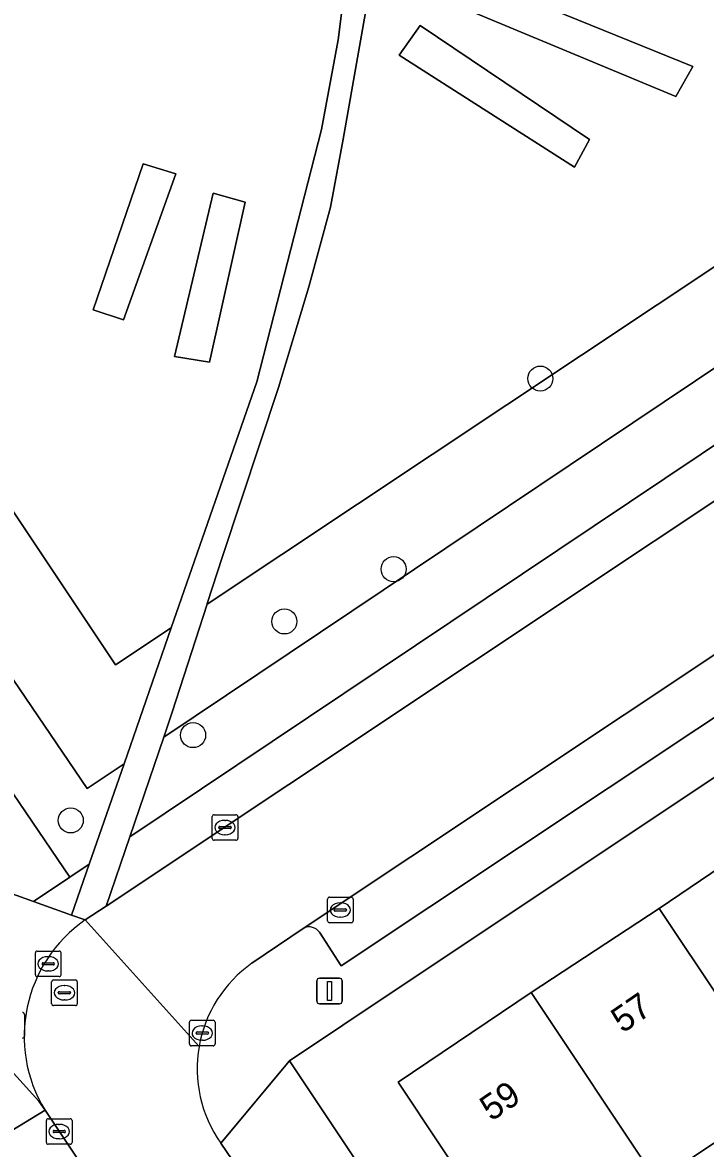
# Model space of a CAD drawing. Extents: x 158352 to 159489, y 383828 to 384603.
# Drawn here: x 158635.92 to 158662.61, y 384326.59 to 384370.6 of the extents above; entities that cross this region are included whole.
import ezdxf

# ---------------------------------------------------------------- set-up
doc = ezdxf.new("R2010")
doc.units = 0
for name, color, linetype in [('IMGEO_Boom', 7, 'Continuous'), ('IMGEO_Erf', 7, 'Continuous'), ('IMGEO_Groenvoorziening', 7, 'Continuous'), ('IMGEO_Kolk', 7, 'Continuous'), ('IMGEO_Lichtmast', 7, 'Continuous'), ('IMGEO_Pand', 7, 'Continuous'), ('IMGEO_Pand_nummerreeks', 7, 'Continuous'), ('IMGEO_Parkeervlak_open', 7, 'Continuous'), ('IMGEO_Rijbaan_lokaal_open', 7, 'Continuous'), ('IMGEO_Rioolput', 7, 'Continuous'), ('IMGEO_Voetpad_onverhard', 7, 'Continuous'), ('IMGEO_Voetpad_open', 7, 'Continuous')]:
    doc.layers.add(name, color=color, linetype=linetype)

msp = doc.modelspace()

# ---------------------------------------------------------------- linework, layer by layer
at = {"layer": 'IMGEO_Boom'}
for centre in [(158656.156, 384356.679), (158650.421, 384349.23), (158646.15, 384347.185), (158642.583, 384342.742), (158637.802, 384339.408)]:
    msp.add_circle(centre, 0.489, dxfattribs=at)
at = {"layer": 'IMGEO_Erf'}
for points in [[(158686.972, 384357.1), (158650.515, 384332.795), (158646.346, 384330.011), (158661.096, 384307.894), (158665.725, 384310.981), (158664.658, 384312.562), (158668.339, 384315.047), (158669.406, 384313.466), (158670.698, 384314.313), (158669.645, 384315.894), (158673.315, 384318.339), (158674.369, 384316.758), (158675.159, 384317.285), (158674.106, 384318.866), (158677.844, 384321.359), (158678.895, 384319.777), (158680.185, 384320.637), (158679.133, 384322.219), (158682.821, 384324.669), (158683.873, 384323.087), (158685.166, 384323.963), (158684.114, 384325.544), (158687.812, 384328.006)], [(158689.651, 384344.598), (158684.664, 384341.256), (158680.179, 384338.27), (158675.175, 384334.952), (158670.192, 384331.631), (158665.697, 384328.629), (158660.712, 384325.314), (158655.487, 384321.833), (158650.601, 384329.173), (158655.799, 384332.679), (158660.8, 384335.97), (158665.278, 384338.996), (158670.262, 384342.316), (158675.277, 384345.618), (158679.76, 384348.606), (158684.738, 384351.963), (158689.934, 384355.386)]]:
    msp.add_lwpolyline(points, dxfattribs=at)
at = {"layer": 'IMGEO_Groenvoorziening'}
for points in [[(158612.277, 384370.752), (158623.109, 384354.586), (158624.609, 384352.34), (158635.047, 384336.712), (158636.346, 384336.245), (158637.768, 384337.197), (158615.983, 384369.264), (158618.23, 384370.405), (158619.305, 384370.951), (158623.296, 384369.846), (158639.55, 384345.488), (158641.728, 384346.935), (158645.068, 384356.551), (158647.597, 384366.42), (158648.253, 384369.918), (158649.315, 384378.279)], [(158649.645, 384372.857), (158648.447, 384366.032), (158647.954, 384363.379), (158647.108, 384360.265), (158645.92, 384356.335), (158643.727, 384349.72), (158643.137, 384347.891), (158643.13, 384347.868), (158675.357, 384369.296), (158675.482, 384369.379), (158675.607, 384369.462), (158685.2, 384375.84)], [(158655.789, 384299.623), (158654.177, 384302.038), (158650.939, 384299.878), (158646.519, 384296.93), (158646.165, 384296.695), (158641.933, 384303.831), (158625.907, 384327.948), (158630.193, 384330.83), (158633.416, 384326.021), (158636.795, 384328.082), (158636.558, 384328.441), (158632.848, 384332.513), (158632.059, 384333.379), (158631.306, 384334.206), (158629.143, 384337.169), (158626.934, 384335.692), (158623.71, 384333.537), (158623.249, 384334.228), (158622.197, 384333.53), (158615.965, 384329.394), (158617.034, 384327.728), (158608.81, 384322.397), (158607.768, 384323.954), (158600.545, 384319.161)]]:
    msp.add_lwpolyline(points, dxfattribs=at)
for points in [[(158670.801, 384362.332), (158671.801, 384363.005), (158686.987, 384373.219), (158685.2, 384375.84), (158675.607, 384369.462), (158675.482, 384369.379), (158675.357, 384369.296), (158643.13, 384347.868), (158641.769, 384343.646), (158641.434, 384342.662)], [(158688.395, 384371.153), (158686.987, 384373.219), (158671.801, 384363.005), (158670.801, 384362.332), (158641.434, 384342.662), (158640.109, 384338.766), (158672.19, 384360.253), (158673.196, 384360.93)], [(158652.15, 384371.583), (158661.451, 384367.698), (158662.118, 384368.88), (158652.628, 384372.736)], [(158662.118, 384368.88), (158661.451, 384367.698), (158652.15, 384371.583), (158652.628, 384372.736)], [(158623.296, 384369.846), (158619.305, 384370.951), (158618.23, 384370.405), (158638.44, 384340.656), (158639.882, 384341.62), (158641.728, 384346.935), (158639.55, 384345.488)], [(158618.23, 384370.405), (158615.983, 384369.264), (158637.768, 384337.197), (158638.521, 384337.701), (158639.882, 384341.62), (158638.44, 384340.656)], [(158650.639, 384369.326), (158657.487, 384364.937), (158658.081, 384366.022), (158651.461, 384370.476)], [(158658.081, 384366.022), (158657.487, 384364.937), (158650.639, 384369.326), (158651.461, 384370.476)], [(158638.678, 384359.361), (158639.862, 384358.98), (158641.905, 384364.681), (158640.63, 384365.073)], [(158638.678, 384359.361), (158640.63, 384365.073), (158641.905, 384364.681), (158639.862, 384358.98)], [(158643.362, 384363.92), (158641.85, 384357.546), (158643.23, 384357.316), (158644.614, 384363.577)], [(158643.362, 384363.92), (158644.614, 384363.577), (158643.23, 384357.316), (158641.85, 384357.546)], [(158638.521, 384337.701), (158637.768, 384337.197), (158636.346, 384336.245), (158637.83, 384335.712)], [(158636.795, 384328.082), (158633.416, 384326.021), (158630.193, 384330.83), (158625.907, 384327.948), (158641.933, 384303.831), (158646.165, 384296.695), (158646.519, 384296.93), (158650.939, 384299.878), (158654.177, 384302.038)]]:
    msp.add_lwpolyline(points, close=True, dxfattribs=at)
at = {"layer": 'IMGEO_Kolk'}
for p, q in [((158643.33, 384338.706), (158643.33, 384339.558)), ((158643.405, 384339.632), (158644.257, 384339.632)), ((158643.818, 384339.412), (158643.843, 384339.412)), ((158644.331, 384339.558), (158644.331, 384338.706)), ((158643.589, 384339.126), (158643.589, 384339.138)), ((158644.027, 384339.089), (158643.629, 384339.089)), ((158643.632, 384339.175), (158644.03, 384339.175)), ((158644.073, 384339.138), (158644.073, 384339.126)), ((158644.257, 384338.632), (158643.405, 384338.632)), ((158643.841, 384338.852), (158643.816, 384338.852)), ((158647.839, 384335.483), (158647.839, 384336.335)), ((158647.914, 384336.409), (158648.766, 384336.409)), ((158648.84, 384336.335), (158648.84, 384335.483)), ((158648.098, 384335.903), (158648.098, 384335.915)), ((158648.536, 384335.866), (158648.138, 384335.866)), ((158648.141, 384335.952), (158648.539, 384335.952)), ((158648.327, 384336.189), (158648.352, 384336.189)), ((158648.582, 384335.915), (158648.582, 384335.903)), ((158648.766, 384335.409), (158647.914, 384335.409)), ((158648.35, 384335.629), (158648.325, 384335.629)), ((158642.44, 384330.671), (158642.44, 384331.523)), ((158642.515, 384331.597), (158643.367, 384331.597)), ((158643.441, 384331.523), (158643.441, 384330.671)), ((158642.699, 384331.091), (158642.699, 384331.103)), ((158643.137, 384331.054), (158642.739, 384331.054)), ((158642.742, 384331.14), (158643.14, 384331.14)), ((158642.928, 384331.377), (158642.953, 384331.377)), ((158643.183, 384331.103), (158643.183, 384331.091)), ((158643.367, 384330.597), (158642.515, 384330.597)), ((158642.951, 384330.817), (158642.926, 384330.817)), ((158636.849, 384326.824), (158636.849, 384327.676)), ((158636.924, 384327.75), (158637.776, 384327.75)), ((158637.337, 384327.53), (158637.362, 384327.53)), ((158637.85, 384327.676), (158637.85, 384326.824)), ((158637.108, 384327.244), (158637.108, 384327.256)), ((158637.546, 384327.207), (158637.148, 384327.207)), ((158637.151, 384327.293), (158637.549, 384327.293)), ((158637.592, 384327.256), (158637.592, 384327.244)), ((158637.776, 384326.75), (158636.924, 384326.75)), ((158637.36, 384326.97), (158637.335, 384326.97))]:
    msp.add_line(p, q, dxfattribs=at)
for points in [[(158643.33, 384338.706), (158643.33, 384339.558)], [(158643.405, 384339.632), (158644.257, 384339.632)], [(158644.331, 384339.558), (158644.331, 384338.706)], [(158644.257, 384338.632), (158643.405, 384338.632)], [(158647.839, 384335.483), (158647.839, 384336.335)], [(158647.914, 384336.409), (158648.766, 384336.409)], [(158648.84, 384336.335), (158648.84, 384335.483)], [(158648.766, 384335.409), (158647.914, 384335.409)], [(158642.44, 384330.671), (158642.44, 384331.523)], [(158642.515, 384331.597), (158643.367, 384331.597)], [(158643.441, 384331.523), (158643.441, 384330.671)], [(158643.367, 384330.597), (158642.515, 384330.597)], [(158636.849, 384326.824), (158636.849, 384327.676)], [(158636.924, 384327.75), (158637.776, 384327.75)], [(158637.85, 384327.676), (158637.85, 384326.824)], [(158637.776, 384326.75), (158636.924, 384326.75)]]:
    msp.add_lwpolyline(points, dxfattribs=at)
for centre, radius, start, end in [((158643.407, 384339.556), 0.0765, 91.552, 178.448), ((158643.407, 384339.556), 0.0765, 91.552, 178.448), ((158644.255, 384339.556), 0.0765, 1.552, 88.448), ((158644.255, 384339.556), 0.0765, 1.552, 88.448), ((158643.629, 384339.135), 0.0403, 85.8775, 175.7526), ((158643.626, 384339.125), 0.0366, 178.938, 274.7102), ((158644.03, 384339.132), 0.043, 264.8664, 352.4533), ((158644.034, 384339.137), 0.0386, 1.7309, 96.639), ((158643.407, 384338.708), 0.0765, 181.552, 268.448), ((158643.407, 384338.708), 0.0765, 181.552, 268.448), ((158644.255, 384338.708), 0.0765, 271.552, 358.448), ((158644.255, 384338.708), 0.0765, 271.552, 358.448), ((158647.916, 384336.333), 0.0765, 91.552, 178.448), ((158647.916, 384336.333), 0.0765, 91.552, 178.448), ((158648.764, 384336.333), 0.0765, 1.552, 88.448), ((158648.764, 384336.333), 0.0765, 1.552, 88.448), ((158648.138, 384335.912), 0.0403, 85.8775, 175.7526), ((158648.135, 384335.902), 0.0366, 178.938, 274.7102), ((158648.539, 384335.909), 0.043, 264.8664, 352.4533), ((158648.543, 384335.914), 0.0386, 1.7309, 96.639), ((158647.916, 384335.485), 0.0765, 181.552, 268.448), ((158647.916, 384335.485), 0.0765, 181.552, 268.448), ((158648.764, 384335.485), 0.0765, 271.552, 358.448), ((158648.764, 384335.485), 0.0765, 271.552, 358.448), ((158642.517, 384331.521), 0.0765, 91.552, 178.448), ((158642.517, 384331.521), 0.0765, 91.552, 178.448), ((158643.365, 384331.521), 0.0765, 1.552, 88.448), ((158643.365, 384331.521), 0.0765, 1.552, 88.448), ((158642.739, 384331.1), 0.0403, 85.8775, 175.7526), ((158642.736, 384331.09), 0.0366, 178.938, 274.7102), ((158643.14, 384331.097), 0.043, 264.8664, 352.4533), ((158643.144, 384331.102), 0.0386, 1.7309, 96.639), ((158642.517, 384330.673), 0.0765, 181.552, 268.448), ((158642.517, 384330.673), 0.0765, 181.552, 268.448), ((158643.365, 384330.673), 0.0765, 271.552, 358.448), ((158643.365, 384330.673), 0.0765, 271.552, 358.448), ((158636.926, 384327.674), 0.0765, 91.552, 178.448), ((158636.926, 384327.674), 0.0765, 91.552, 178.448), ((158637.774, 384327.674), 0.0765, 1.552, 88.448), ((158637.774, 384327.674), 0.0765, 1.552, 88.448), ((158637.148, 384327.253), 0.0403, 85.8775, 175.7526), ((158637.145, 384327.243), 0.0366, 178.938, 274.7102), ((158637.549, 384327.25), 0.043, 264.8664, 352.4533), ((158637.553, 384327.255), 0.0386, 1.7309, 96.639), ((158636.926, 384326.826), 0.0765, 181.552, 268.448), ((158636.926, 384326.826), 0.0765, 181.552, 268.448), ((158637.774, 384326.826), 0.0765, 271.552, 358.448), ((158637.774, 384326.826), 0.0765, 271.552, 358.448)]:
    msp.add_arc(centre, radius, start, end, dxfattribs=at)
for centre, major_axis, ratio, start_param, end_param in [((158643.817, 384339.132), (-0.387, 0.002), 0.722429, 4.712389, 7.853982), ((158643.842, 384339.132), (-0.39, 0.002), 0.717154, 1.570796, 4.712389), ((158648.326, 384335.909), (-0.387, 0.002), 0.722429, 4.712389, 7.853982), ((158648.351, 384335.909), (-0.39, 0.002), 0.717154, 1.570796, 4.712389), ((158642.927, 384331.097), (-0.387, 0.002), 0.722429, 4.712389, 7.853982), ((158642.952, 384331.097), (-0.39, 0.002), 0.717154, 1.570796, 4.712389), ((158637.336, 384327.25), (-0.387, 0.002), 0.722429, 4.712389, 7.853982), ((158637.361, 384327.25), (-0.39, 0.002), 0.717154, 1.570796, 4.712389)]:
    msp.add_ellipse(centre, major_axis=major_axis, ratio=ratio, start_param=start_param, end_param=end_param, dxfattribs=at)
at = {"layer": 'IMGEO_Lichtmast'}
for p, q in [((158647.52, 384333.243), (158648.31, 384333.243)), ((158648.31, 384333.243), (158647.52, 384333.243)), ((158647.42, 384332.343), (158647.42, 384333.143)), ((158647.42, 384333.143), (158647.42, 384332.343)), ((158648.41, 384333.143), (158648.41, 384332.343)), ((158648.41, 384332.343), (158648.41, 384333.143)), ((158648.31, 384332.243), (158647.52, 384332.243)), ((158647.52, 384332.243), (158648.31, 384332.243))]:
    msp.add_line(p, q, dxfattribs=at)
msp.add_lwpolyline([(158647.84, 384333.118), (158647.99, 384333.118), (158647.99, 384332.368), (158647.84, 384332.368), (158647.84, 384333.118)], dxfattribs=at)
for centre, start, end in [((158647.52, 384333.143), 90, 180), ((158647.52, 384333.143), 90, 180), ((158648.31, 384333.143), 0, 90), ((158648.31, 384333.143), 360, 90), ((158647.52, 384332.343), 180, 270), ((158647.52, 384332.343), 180, 270), ((158648.31, 384332.343), 270, 0), ((158648.31, 384332.343), 270, 0)]:
    msp.add_arc(centre, 0.1, start, end, dxfattribs=at)
at = {"layer": 'IMGEO_Pand'}
for points in [[(158665.697, 384328.629), (158670.192, 384331.631), (158665.278, 384338.996), (158660.8, 384335.97)], [(158660.8, 384335.97), (158655.799, 384332.679), (158660.712, 384325.314), (158665.697, 384328.629)], [(158655.799, 384332.679), (158650.601, 384329.173), (158655.487, 384321.833), (158660.712, 384325.314)]]:
    msp.add_lwpolyline(points, close=True, dxfattribs=at)
at = {"layer": 'IMGEO_Parkeervlak_open'}
for points in [[(158689.221, 384363.377), (158684.485, 384360.21), (158646.929, 384335.217)], [(158647.518, 384335.038), (158648.374, 384333.728), (158686.654, 384359.199), (158690.04, 384361.478), (158689.167, 384362.842)]]:
    msp.add_lwpolyline(points, dxfattribs=at)
msp.add_arc((158647.108, 384334.746), 0.504, 35.4148, 110.7767, dxfattribs=at)
at = {"layer": 'IMGEO_Rijbaan_lokaal_open'}
for points in [[(158684.485, 384360.21), (158689.221, 384363.377), (158689.364, 384363.473), (158686.591, 384367.607), (158681.988, 384364.56), (158639.19, 384336.064), (158638.37, 384335.518), (158642.816, 384330.568)], [(158644.885, 384333.828), (158646.929, 384335.217), (158684.485, 384360.21)], [(158642.816, 384330.568), (158638.37, 384335.518)], [(158636.795, 384328.082), (158654.177, 384302.038), (158655.789, 384299.623), (158691.316, 384246.356), (158695.508, 384249.16), (158693.594, 384252.04), (158659.086, 384303.74), (158654.809, 384310.191), (158644.803, 384325.125)], [(158644.803, 384325.125), (158643.662, 384326.8)]]:
    msp.add_lwpolyline(points, dxfattribs=at)
for centre, radius, start, end in [((158641.503, 384330.97), 5.523, 124.5632, 211.5189), ((158647.782, 384329.703), 5.041, 125.0782, 170.1183), ((158647.785, 384329.705), 5.043, 170.1422, 215.1665)]:
    msp.add_arc(centre, radius, start, end, dxfattribs=at)
at = {"layer": 'IMGEO_Rioolput'}
for p, q in [((158636.418, 384333.378), (158636.418, 384334.23)), ((158636.493, 384334.304), (158637.345, 384334.304)), ((158636.906, 384334.084), (158636.931, 384334.084)), ((158637.419, 384334.23), (158637.419, 384333.378)), ((158636.677, 384333.798), (158636.677, 384333.81)), ((158637.115, 384333.761), (158636.717, 384333.761)), ((158636.72, 384333.847), (158637.118, 384333.847)), ((158637.161, 384333.81), (158637.161, 384333.798)), ((158637.345, 384333.304), (158636.493, 384333.304)), ((158636.929, 384333.524), (158636.904, 384333.524)), ((158637.054, 384332.246), (158637.054, 384333.098)), ((158637.129, 384333.172), (158637.981, 384333.172)), ((158637.542, 384332.952), (158637.567, 384332.952)), ((158638.055, 384333.098), (158638.055, 384332.246)), ((158637.313, 384332.666), (158637.313, 384332.678)), ((158637.751, 384332.629), (158637.353, 384332.629)), ((158637.356, 384332.715), (158637.754, 384332.715)), ((158637.565, 384332.392), (158637.54, 384332.392)), ((158637.797, 384332.678), (158637.797, 384332.666)), ((158637.981, 384332.172), (158637.129, 384332.172)), ((158635.989, 384331.828), (158635.989, 384330.976))]:
    msp.add_line(p, q, dxfattribs=at)
for points in [[(158636.418, 384333.378), (158636.418, 384334.23)], [(158636.493, 384334.304), (158637.345, 384334.304)], [(158637.419, 384334.23), (158637.419, 384333.378)], [(158637.345, 384333.304), (158636.493, 384333.304)], [(158637.054, 384332.246), (158637.054, 384333.098)], [(158637.129, 384333.172), (158637.981, 384333.172)], [(158638.055, 384333.098), (158638.055, 384332.246)], [(158637.981, 384332.172), (158637.129, 384332.172)], [(158635.989, 384331.828), (158635.989, 384330.976)]]:
    msp.add_lwpolyline(points, dxfattribs=at)
for centre, radius, start, end in [((158636.495, 384334.228), 0.0765, 91.552, 178.448), ((158636.495, 384334.228), 0.0765, 91.552, 178.448), ((158637.343, 384334.228), 0.0765, 1.552, 88.448), ((158637.343, 384334.228), 0.0765, 1.552, 88.448), ((158636.717, 384333.807), 0.0403, 85.8775, 175.7526), ((158636.714, 384333.797), 0.0366, 178.938, 274.7102), ((158637.118, 384333.804), 0.043, 264.8664, 352.4533), ((158637.122, 384333.809), 0.0386, 1.7309, 96.639), ((158636.495, 384333.38), 0.0765, 181.552, 268.448), ((158636.495, 384333.38), 0.0765, 181.552, 268.448), ((158637.343, 384333.38), 0.0765, 271.552, 358.448), ((158637.343, 384333.38), 0.0765, 271.552, 358.448), ((158637.131, 384333.096), 0.0765, 91.552, 178.448), ((158637.131, 384333.096), 0.0765, 91.552, 178.448), ((158637.979, 384333.096), 0.0765, 1.552, 88.448), ((158637.979, 384333.096), 0.0765, 1.552, 88.448), ((158637.353, 384332.675), 0.0403, 85.8775, 175.7526), ((158637.35, 384332.665), 0.0366, 178.938, 274.7102), ((158637.754, 384332.672), 0.043, 264.8664, 352.4533), ((158637.758, 384332.677), 0.0386, 1.7309, 96.639), ((158635.913, 384331.826), 0.0765, 1.552, 88.448), ((158635.913, 384331.826), 0.0765, 1.552, 88.448), ((158637.131, 384332.248), 0.0765, 181.552, 268.448), ((158637.131, 384332.248), 0.0765, 181.552, 268.448), ((158637.979, 384332.248), 0.0765, 271.552, 358.448), ((158637.979, 384332.248), 0.0765, 271.552, 358.448), ((158635.913, 384330.978), 0.0765, 271.552, 358.448), ((158635.913, 384330.978), 0.0765, 271.552, 358.448)]:
    msp.add_arc(centre, radius, start, end, dxfattribs=at)
for centre, major_axis, ratio, start_param, end_param in [((158636.905, 384333.804), (-0.387, 0.002), 0.722429, 4.712389, 7.853982), ((158636.93, 384333.804), (-0.39, 0.002), 0.717154, 1.570796, 4.712389), ((158637.541, 384332.672), (-0.387, 0.002), 0.722429, 4.712389, 7.853982), ((158637.566, 384332.672), (-0.39, 0.002), 0.717154, 1.570796, 4.712389)]:
    msp.add_ellipse(centre, major_axis=major_axis, ratio=ratio, start_param=start_param, end_param=end_param, dxfattribs=at)
at = {"layer": 'IMGEO_Voetpad_onverhard'}
msp.add_lwpolyline([(158649.315, 384378.279), (158648.253, 384369.918), (158647.597, 384366.42), (158645.068, 384356.551), (158641.728, 384346.935), (158639.882, 384341.62), (158638.521, 384337.701), (158637.83, 384335.712), (158638.37, 384335.518), (158639.19, 384336.064), (158640.109, 384338.766), (158641.434, 384342.662), (158641.769, 384343.646), (158643.13, 384347.868), (158643.137, 384347.891), (158643.727, 384349.72), (158645.92, 384356.335), (158647.108, 384360.265), (158647.954, 384363.379), (158648.447, 384366.032), (158649.645, 384372.857)], dxfattribs=at)
at = {"layer": 'IMGEO_Voetpad_open'}
for points in [[(158756.032, 384416.448), (158743.282, 384407.89), (158742.278, 384407.217), (158716.954, 384390.243), (158715.642, 384389.377), (158707.798, 384384.134), (158704.964, 384382.243), (158698.179, 384377.716), (158694.831, 384375.482), (158688.395, 384371.153), (158673.196, 384360.93), (158672.19, 384360.253), (158640.109, 384338.766), (158639.19, 384336.064), (158681.988, 384364.56), (158686.591, 384367.607), (158706.188, 384380.69), (158744.541, 384406.289), (158761.522, 384417.613)], [(158689.167, 384362.842), (158690.04, 384361.478), (158686.654, 384359.199), (158648.374, 384333.728), (158647.518, 384335.038)], [(158643.662, 384326.8), (158646.346, 384330.011), (158650.515, 384332.795), (158686.972, 384357.1)], [(158638.37, 384335.518), (158637.83, 384335.712), (158636.346, 384336.245), (158635.047, 384336.712), (158634.799, 384336.801), (158631.306, 384334.206), (158632.059, 384333.379), (158632.848, 384332.513), (158636.558, 384328.441), (158636.795, 384328.082)], [(158646.929, 384335.217), (158644.885, 384333.828)], [(158661.89, 384306.702), (158661.096, 384307.894), (158646.346, 384330.011), (158643.662, 384326.8), (158644.803, 384325.125)]]:
    msp.add_lwpolyline(points, dxfattribs=at)
for centre, radius, start, end in [((158641.503, 384330.97), 5.523, 124.5632, 211.5189), ((158647.108, 384334.746), 0.504, 35.4148, 110.7767), ((158647.782, 384329.703), 5.041, 125.0782, 170.1183), ((158647.785, 384329.705), 5.043, 170.1422, 215.1665)]:
    msp.add_arc(centre, radius, start, end, dxfattribs=at)

# ---------------------------------------------------------------- texts
at = {"layer": 'IMGEO_Pand_nummerreeks'}
for s, rotation, p in [('57', 34.4925, (158659.37, 384331.069)), ('59', 34.3482, (158654.237, 384327.623))]:
    msp.add_text(s, height=1, rotation=rotation, dxfattribs=at).set_placement(p)

doc.saveas('drawing.dxf')
